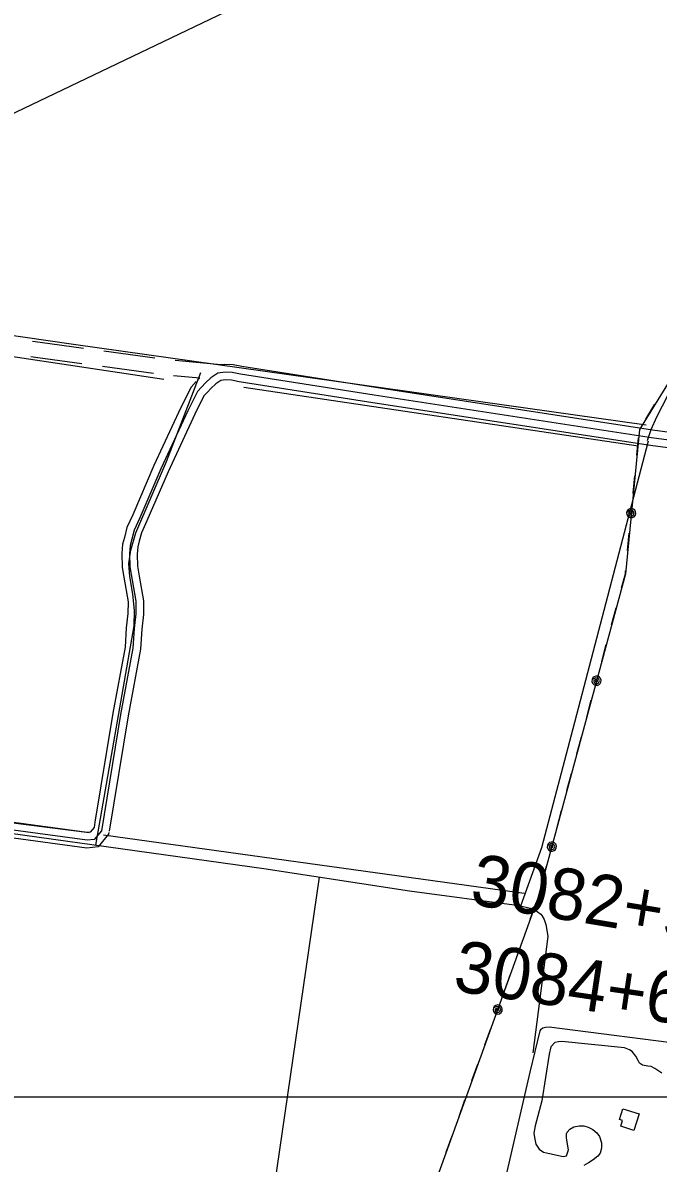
# Model space of a CAD drawing. Extents: x 3279314 to 3317160, y 734079 to 759431.
# Drawn here: x 3292879 to 3294115, y 745391 to 747608 of the extents above; entities that cross this region are included whole.
import ezdxf

# ---------------------------------------------------------------- set-up
doc = ezdxf.new("R2010")
doc.units = 0
for name, color, linetype in [('V-BLDG-OTLN', 7, 'Continuous'), ('V-DTCH-CNTR', 7, 'Continuous'), ('V-GRID-MAJR', 7, 'Continuous'), ('V-ROAD-CNTR', 7, 'Continuous'), ('V-SITE-VEGE', 7, 'Continuous'), ('V-SURV-IDEN', 7, 'Continuous'), ('V-TOPO-SHOR', 7, 'Continuous'), ('V-UTIL-LINE', 7, 'Continuous')]:
    doc.layers.add(name, color=color, linetype=linetype)

msp = doc.modelspace()

# ---------------------------------------------------------------- linework, layer by layer
at = {"layer": 'V-BLDG-OTLN'}
msp.add_lwpolyline([(3294046.1, 745496.6), (3294077.5, 745486.6), (3294067.3, 745454.5), (3294041.9, 745462.6), (3294045.3, 745473.5), (3294039.3, 745475.4)], close=True, dxfattribs=at)
at = {"layer": 'V-DTCH-CNTR'}
for points in [[(3294093.7, 746795.9), (3294100.8, 746817.4), (3294112.1, 746842.3), (3294134, 746884.8), (3294317.1, 747143.4), (3294354.6, 747199.3), (3294407, 747286.1), (3294470, 747391.3), (3294520.1, 747482.2), (3294563.8, 747576.8), (3294595.6, 747657), (3294614.4, 747737.2), (3294630.7, 747802.9)], [(3293021.2, 746009.2), (3293095.7, 746435.6), (3293096.8, 746465.4), (3293093.2, 746497.3), (3293087.2, 746531.3), (3293085.6, 746557), (3293089.1, 746582.6), (3293099, 746616.4), (3293158.5, 746755.5), (3293225.6, 746928.4)], [(3293847.8, 745891.3), (3293888.6, 746004.8), (3293952.6, 746248.1), (3294095.6, 746795.7)], [(3291464.3, 746222.2), (3291703.7, 746193.6), (3292081.2, 746138.6), (3292631.9, 746063.4), (3293348.1, 745963.7), (3293631.4, 745920.6), (3293844.5, 745892.1), (3293865.5, 745886.6), (3293879.2, 745880.2), (3293886.3, 745874.9), (3293888.3, 745872.3), (3293893.3, 745864.5), (3293896.2, 745854.7), (3293897.6, 745847.5), (3293900.4, 745831.5), (3293871.2, 745605.1)], [(3293101.5, 743772.6), (3293170.6, 744118.5), (3293224.8, 744450.9), (3293338.3, 745136), (3293456.5, 745947.2)]]:
    msp.add_lwpolyline(points, dxfattribs=at)
at = {"layer": 'V-GRID-MAJR'}
msp.add_spline([(3283456.6, 745517.7), (3286079.8, 745518), (3291326.2, 745519.1), (3296572.6, 745521), (3301819.1, 745523.7), (3307065.5, 745527.1), (3312312, 745531.3), (3314935.2, 745533.7)], degree=3, dxfattribs=at)
at = {"layer": 'V-ROAD-CNTR'}
for p, q in [((3293136.1, 746956.4), (3293037, 746969.8)), ((3293133.2, 746926.6), (3293034.1, 746939.9)), ((3293271.8, 746942.5), (3293175.3, 746951.8)), ((3293223.5, 746917), (3293172.3, 746921.9))]:
    msp.add_line(p, q, dxfattribs=at)
for points in [[(3292997.3, 746975.2), (3292912.9, 746986.6), (3292898.3, 746988.7)], [(3292994.4, 746945.3), (3292908.7, 746956.9), (3292895.3, 746958.8)], [(3295076.8, 746656.9), (3295042.6, 746678.8), (3295000.9, 746687.8), (3294899.3, 746703.5), (3294426.7, 746772.9), (3294103.9, 746816.1), (3293564.8, 746898.8), (3293305.2, 746939.9), (3293288.5, 746943), (3293272.2, 746944), (3293265.2, 746943.1)], [(3294424.6, 746758.1), (3294101.7, 746801.2), (3293562.4, 746884), (3293302.6, 746925.1), (3293286.6, 746928.1), (3293272.7, 746928.9), (3293258.6, 746927.1), (3293245.1, 746917.8), (3293234.4, 746907.9), (3293218.9, 746891.3), (3293200.2, 746853.5), (3293148, 746741.1), (3293106.7, 746645.6), (3293096, 746621.7), (3293091.4, 746604), (3293088.4, 746591.7), (3293087, 746575.5), (3293087.5, 746550.3), (3293099.3, 746483.4), (3293098.8, 746458.9), (3293095.6, 746430.5), (3293093.4, 746392.4), (3293069.4, 746263.2), (3293032.1, 746037), (3293018, 746020.1), (3293004.2, 746018.7), (3292620.2, 746070.6)], [(3294424.6, 746758.1), (3294101.7, 746801.2), (3293562.4, 746884), (3293302.6, 746925.1), (3293286.6, 746928.1), (3293272.7, 746928.9), (3293258.6, 746927.1), (3293245.1, 746917.8), (3293234.4, 746907.9), (3293218.9, 746891.3), (3293200.2, 746853.5), (3293148, 746741.1), (3293106.7, 746645.6), (3293096, 746621.7), (3293091.4, 746604), (3293088.4, 746591.7), (3293087, 746575.5), (3293087.5, 746550.3), (3293099.3, 746483.4), (3293098.8, 746458.9), (3293095.6, 746430.5), (3293093.4, 746392.4), (3293069.4, 746263.2), (3293032.1, 746037), (3293018, 746020.1), (3293004.2, 746018.7), (3292620.2, 746070.6)], [(3293216.3, 746910.5), (3293206.4, 746899.9), (3293186.7, 746860), (3293134.3, 746747.2), (3293093, 746651.7), (3293081.7, 746626.7), (3293076.8, 746607.6), (3293073.5, 746594.2), (3293072, 746576), (3293072.5, 746548.9), (3293075.7, 746530.6)], [(3293222.6, 746917.3), (3293218.7, 746913.1)], [(3295060.6, 746631.6), (3295031, 746650.6), (3294995.5, 746658.3), (3294894.8, 746673.8), (3294422.6, 746743.2), (3294099.6, 746786.4), (3293560.1, 746869.2), (3293300.1, 746910.3), (3293284.8, 746913.1), (3293273.2, 746913.9), (3293264.1, 746912.7), (3293254.5, 746906), (3293244.9, 746897.2), (3293238.9, 746890.7)], [(3293238.9, 746890.7), (3293231.4, 746882.6), (3293213.7, 746847), (3293161.7, 746735), (3293120.4, 746639.6), (3293110.2, 746616.7), (3293105.9, 746600.3), (3293103.2, 746589.3), (3293102, 746575), (3293102.5, 746551.8), (3293105.9, 746532.3)], [(3293105.9, 746532.3), (3293114.3, 746484.6), (3293113.8, 746457.9), (3293110.5, 746429.2), (3293108.3, 746390.6), (3293084.2, 746260.6), (3293047.2, 746036.3)], [(3293075.7, 746530.6), (3293084.3, 746482.2), (3293083.8, 746459.9), (3293080.6, 746431.7), (3293078.5, 746394.2), (3293054.6, 746265.8), (3293019.7, 746054.1)], [(3293019.7, 746054.1), (3293017.9, 746043.5), (3293010.4, 746034.4), (3293004.5, 746033.8), (3292622.3, 746085.4), (3292014.2, 746170.6), (3291393.3, 746255.9), (3291177.8, 746289.7), (3291124.8, 746305.9)], [(3293046.8, 746033.9), (3293046.2, 746030.6), (3293025.6, 746005.7), (3293003.9, 746003.6), (3292618.2, 746055.7), (3292010.1, 746140.8), (3291478.3, 746214)]]:
    msp.add_lwpolyline(points, dxfattribs=at)
at = {"layer": 'V-SITE-VEGE'}
for points in [[(3293816.9, 745356.9), (3293865.9, 745568), (3293885.1, 745648), (3293887.1, 745651.5), (3293890.5, 745654.2), (3293895.5, 745655.5), (3293903, 745655.8)], [(3293903, 745655.8), (3294186.1, 745619.5)], [(3294121.9, 745565.8), (3294113.9, 745571.2), (3294108.3, 745574.6), (3294101.1, 745578.5), (3294094.3, 745579.5), (3294084.5, 745581.2), (3294078.4, 745585.5), (3294076.1, 745590.6), (3294071.4, 745598.8), (3294064.3, 745607.7), (3294058.9, 745611.5), (3294048.9, 745615.2), (3293927.5, 745627.2), (3293920.9, 745626.5), (3293913.6, 745625.3), (3293906, 745616.7), (3293902.7, 745602.5), (3293888.8, 745512.1), (3293875.2, 745463.2), (3293873.2, 745449.4), (3293874.3, 745440.8), (3293877, 745428), (3293883.1, 745417.8), (3293891.8, 745412.4), (3293903.6, 745409.5), (3293929.9, 745404), (3293936.3, 745405.2), (3293940.2, 745417), (3293937.2, 745435.7), (3293936.7, 745440.5), (3293936.6, 745447.8), (3293937.7, 745451.1), (3293943.1, 745456.9), (3293950.9, 745461.4), (3293961.2, 745463.6), (3293970.2, 745463.2), (3293978.5, 745461.1)], [(3293978.5, 745461.1), (3293987.6, 745456.1), (3293995.4, 745449.6), (3294000.6, 745442.7), (3294004.3, 745430.6), (3294004.8, 745419.8), (3294002, 745410.2), (3293997.2, 745404.6), (3293988.1, 745397.5), (3293979.2, 745391.5), (3293970.4, 745386.4)]]:
    msp.add_lwpolyline(points, dxfattribs=at)
at = {"layer": 'V-TOPO-SHOR'}
for p, q in [((3292978, 746982.7), (3292483.2, 747053.3)), ((3292475.3, 747017.4), (3293153.7, 746915.3)), ((3294091.3, 746825.7), (3292978, 746982.7)), ((3293309.3, 746899.7), (3294075.5, 746785.8)), ((3293036.1, 746029.4), (3293854.1, 745915.7))]:
    msp.add_line(p, q, dxfattribs=at)
msp.add_lwpolyline([(3293008.2, 746033.3), (3292696.9, 746072.5), (3292082.5, 746154.8)], dxfattribs=at)
at = {"layer": 'V-UTIL-LINE'}
for points in [[(3294823.7, 749101.3), (3294567, 747672.2), (3294455.7, 747427.9), (3294078.1, 746817.4), (3294050.9, 746537.1), (3293880.8, 745906.1), (3293685, 745363.8), (3293337.1, 745210.6), (3293161, 744222.1), (3293091.7, 743807.4)], [(3288668.1, 745426), (3296052.2, 748960.2), (3296218.4, 748982.8)], [(3294090.5, 746837.5), (3294108.4, 746866.4)], [(3294073.2, 746767.3), (3294076.5, 746801.1)], [(3294066.1, 746693.6), (3294069.4, 746727.5)], [(3294062.3, 746654.8), (3294059.8, 746653.4), (3294061.9, 746652.4), (3294064.3, 746653.8), (3294064.2, 746656.7), (3294060.9, 746657.2), (3294057.2, 746654.3), (3294058.6, 746650.3), (3294063.1, 746648.5), (3294066.8, 746651.3), (3294068.2, 746655.5), (3294065.5, 746659.5), (3294060.1, 746660.4), (3294053.4, 746655.7), (3294053.7, 746652.2), (3294055.4, 746649.1), (3294058.1, 746646.8), (3294061.5, 746645.8), (3294065, 746646.2), (3294068.1, 746647.8), (3294070.3, 746650.6), (3294071.3, 746653.9), (3294070.9, 746657.4), (3294069.3, 746660.5), (3294066.6, 746662.7), (3294063.2, 746663.8), (3294059.7, 746663.4), (3294056.6, 746661.7), (3294054.4, 746659), (3294053.4, 746655.7)], [(3294055.3, 746582.1), (3294058.6, 746616)], [(3294043.4, 746509.3), (3294050.9, 746537.1), (3294051.4, 746542.3)], [(3294024.2, 746437.9), (3294033, 746470.7)], [(3294004.9, 746366.4), (3294013.8, 746399.3)], [(3293994.8, 746328.8), (3293992.1, 746327.8), (3293994, 746326.5), (3293996.5, 746327.5), (3293997, 746330.3), (3293993.7, 746331.4), (3293989.6, 746329.2), (3293990.3, 746324.9), (3293994.5, 746322.5), (3293998.6, 746324.6), (3294000.7, 746328.5), (3293998.7, 746332.9), (3293993.4, 746334.6), (3293986.1, 746331.1), (3293985.8, 746327.6), (3293987, 746324.3), (3293989.3, 746321.7), (3293992.4, 746320.1), (3293995.9, 746319.9), (3293999.3, 746321), (3294001.9, 746323.3), (3294003.5, 746326.4), (3294003.7, 746329.9), (3294002.6, 746333.3), (3294000.3, 746335.9), (3293997.1, 746337.5), (3293993.6, 746337.7), (3293990.3, 746336.6), (3293987.6, 746334.3), (3293986.1, 746331.1)], [(3293975.8, 746258.3), (3293984.6, 746291.1)], [(3293956.5, 746186.8), (3293965.4, 746219.7)], [(3293937.3, 746115.4), (3293946.1, 746148.2)], [(3293918, 746044), (3293926.8, 746076.8)], [(3293907.8, 746006.3), (3293905.1, 746005.3), (3293907, 746004), (3293909.6, 746005), (3293910, 746007.9), (3293906.8, 746008.9), (3293902.7, 746006.7), (3293903.4, 746002.5), (3293907.6, 746000), (3293911.7, 746002.1), (3293913.7, 746006), (3293911.7, 746010.4), (3293906.5, 746012.2), (3293899.2, 746008.6), (3293898.9, 746005.1), (3293900, 746001.8), (3293902.4, 745999.2), (3293905.5, 745997.6), (3293909, 745997.4), (3293912.3, 745998.5), (3293915, 746000.8), (3293916.5, 746004), (3293916.8, 746007.5), (3293915.6, 746010.8), (3293913.3, 746013.4), (3293910.2, 746015), (3293906.7, 746015.2), (3293903.4, 746014.1), (3293900.7, 746011.8), (3293899.2, 746008.6)], [(3293888.8, 745935.8), (3293897.7, 745968.6)], [(3293866.1, 745865.4), (3293877.7, 745897.4)], [(3293841, 745795.8), (3293852.6, 745827.8)], [(3293815.9, 745726.2), (3293827.4, 745758.2)], [(3293802.6, 745689.6), (3293799.9, 745688.8), (3293801.6, 745687.3), (3293804.3, 745688.1), (3293805, 745690.9), (3293801.8, 745692.2), (3293797.5, 745690.4), (3293797.9, 745686.1), (3293801.8, 745683.3), (3293806.1, 745685), (3293808.5, 745688.8), (3293806.9, 745693.3), (3293801.8, 745695.5), (3293794.2, 745692.6), (3293793.6, 745689.1), (3293794.5, 745685.7), (3293796.6, 745682.9), (3293799.6, 745681.1), (3293803, 745680.6), (3293806.5, 745681.4), (3293809.3, 745683.5), (3293811.1, 745686.5), (3293811.6, 745690), (3293810.8, 745693.4), (3293808.7, 745696.2), (3293805.7, 745698), (3293802.2, 745698.5), (3293798.8, 745697.7), (3293796, 745695.6), (3293794.2, 745692.6)], [(3293777.8, 745620.9), (3293789.4, 745652.9)], [(3293752.7, 745551.3), (3293764.3, 745583.3)], [(3293727.6, 745481.7), (3293739.1, 745513.7)], [(3293702.4, 745412.1), (3293714, 745444.1)]]:
    msp.add_lwpolyline(points, dxfattribs=at)

# ---------------------------------------------------------------- texts
at = {"layer": 'V-SURV-IDEN'}
for s, rotation, p in [('3082+90.5', 350.5919, (3293746.4, 745894.8)), ('3084+67.7', 351.5278, (3293713.7, 745726.4))]:
    msp.add_text(s, height=100, rotation=rotation, dxfattribs=at).set_placement(p)

doc.saveas('drawing.dxf')
